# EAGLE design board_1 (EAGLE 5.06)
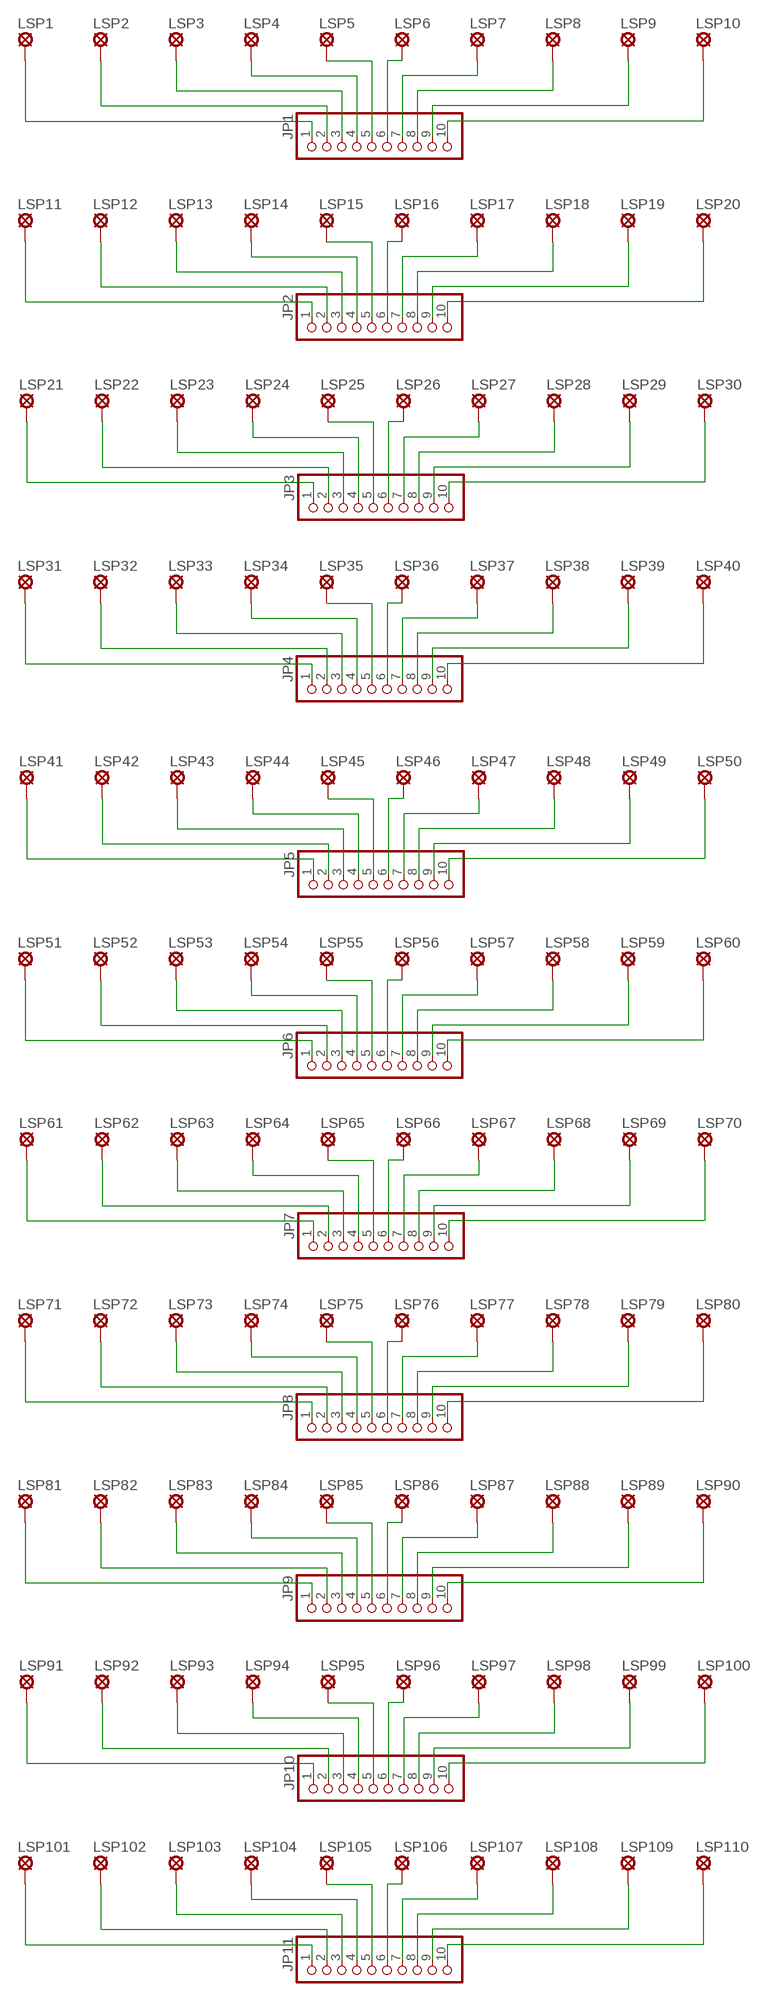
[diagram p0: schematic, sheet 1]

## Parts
JP1  PINHD-1X10  [1X10]
JP2  PINHD-1X10  [1X10]
JP3  PINHD-1X10  [1X10]
JP4  PINHD-1X10  [1X10]
JP5  PINHD-1X10  [1X10]
JP6  PINHD-1X10  [1X10]
JP7  PINHD-1X10  [1X10]
JP8  PINHD-1X10  [1X10]
JP9  PINHD-1X10  [1X10]
JP10  PINHD-1X10  [1X10]
JP11  PINHD-1X10  [1X10]
LSP1  LSP10MEDIUM_PAD2  [MEDIUM_PAD]
LSP2  LSP10MEDIUM_PAD2  [MEDIUM_PAD]
LSP3  LSP10MEDIUM_PAD2  [MEDIUM_PAD]
LSP4  LSP10MEDIUM_PAD2  [MEDIUM_PAD]
LSP5  LSP10MEDIUM_PAD2  [MEDIUM_PAD]
LSP6  LSP10MEDIUM_PAD2  [MEDIUM_PAD]
LSP7  LSP10MEDIUM_PAD2  [MEDIUM_PAD]
LSP8  LSP10MEDIUM_PAD2  [MEDIUM_PAD]
LSP9  LSP10MEDIUM_PAD2  [MEDIUM_PAD]
LSP10  LSP10MEDIUM_PAD2  [MEDIUM_PAD]
LSP11  LSP10MEDIUM_PAD2  [MEDIUM_PAD]
LSP12  LSP10MEDIUM_PAD2  [MEDIUM_PAD]
LSP13  LSP10MEDIUM_PAD2  [MEDIUM_PAD]
LSP14  LSP10MEDIUM_PAD2  [MEDIUM_PAD]
LSP15  LSP10MEDIUM_PAD2  [MEDIUM_PAD]
LSP16  LSP10MEDIUM_PAD2  [MEDIUM_PAD]
LSP17  LSP10MEDIUM_PAD2  [MEDIUM_PAD]
LSP18  LSP10MEDIUM_PAD2  [MEDIUM_PAD]
LSP19  LSP10MEDIUM_PAD2  [MEDIUM_PAD]
LSP20  LSP10MEDIUM_PAD2  [MEDIUM_PAD]
LSP21  LSP10MEDIUM_PAD2  [MEDIUM_PAD]
LSP22  LSP10MEDIUM_PAD2  [MEDIUM_PAD]
LSP23  LSP10MEDIUM_PAD2  [MEDIUM_PAD]
LSP24  LSP10MEDIUM_PAD2  [MEDIUM_PAD]
LSP25  LSP10MEDIUM_PAD2  [MEDIUM_PAD]
LSP26  LSP10MEDIUM_PAD2  [MEDIUM_PAD]
LSP27  LSP10MEDIUM_PAD2  [MEDIUM_PAD]
LSP28  LSP10MEDIUM_PAD2  [MEDIUM_PAD]
LSP29  LSP10MEDIUM_PAD2  [MEDIUM_PAD]
LSP30  LSP10MEDIUM_PAD2  [MEDIUM_PAD]
LSP31  LSP10MEDIUM_PAD2  [MEDIUM_PAD]
LSP32  LSP10MEDIUM_PAD2  [MEDIUM_PAD]
LSP33  LSP10MEDIUM_PAD2  [MEDIUM_PAD]
LSP34  LSP10MEDIUM_PAD2  [MEDIUM_PAD]
LSP35  LSP10MEDIUM_PAD2  [MEDIUM_PAD]
LSP36  LSP10MEDIUM_PAD2  [MEDIUM_PAD]
LSP37  LSP10MEDIUM_PAD2  [MEDIUM_PAD]
LSP38  LSP10MEDIUM_PAD2  [MEDIUM_PAD]
LSP39  LSP10MEDIUM_PAD2  [MEDIUM_PAD]
LSP40  LSP10MEDIUM_PAD2  [MEDIUM_PAD]
LSP41  LSP10MEDIUM_PAD2  [MEDIUM_PAD]
LSP42  LSP10MEDIUM_PAD2  [MEDIUM_PAD]
LSP43  LSP10MEDIUM_PAD2  [MEDIUM_PAD]
LSP44  LSP10MEDIUM_PAD2  [MEDIUM_PAD]
LSP45  LSP10MEDIUM_PAD2  [MEDIUM_PAD]
LSP46  LSP10MEDIUM_PAD2  [MEDIUM_PAD]
LSP47  LSP10MEDIUM_PAD2  [MEDIUM_PAD]
LSP48  LSP10MEDIUM_PAD2  [MEDIUM_PAD]
LSP49  LSP10MEDIUM_PAD2  [MEDIUM_PAD]
LSP50  LSP10MEDIUM_PAD2  [MEDIUM_PAD]
LSP51  LSP10MEDIUM_PAD2  [MEDIUM_PAD]
LSP52  LSP10MEDIUM_PAD2  [MEDIUM_PAD]
LSP53  LSP10MEDIUM_PAD2  [MEDIUM_PAD]
LSP54  LSP10MEDIUM_PAD2  [MEDIUM_PAD]
LSP55  LSP10MEDIUM_PAD2  [MEDIUM_PAD]
LSP56  LSP10MEDIUM_PAD2  [MEDIUM_PAD]
LSP57  LSP10MEDIUM_PAD2  [MEDIUM_PAD]
LSP58  LSP10MEDIUM_PAD2  [MEDIUM_PAD]
LSP59  LSP10MEDIUM_PAD2  [MEDIUM_PAD]
LSP60  LSP10MEDIUM_PAD2  [MEDIUM_PAD]
LSP61  LSP10MEDIUM_PAD2  [MEDIUM_PAD]
LSP62  LSP10MEDIUM_PAD2  [MEDIUM_PAD]
LSP63  LSP10MEDIUM_PAD2  [MEDIUM_PAD]
LSP64  LSP10MEDIUM_PAD2  [MEDIUM_PAD]
LSP65  LSP10MEDIUM_PAD2  [MEDIUM_PAD]
LSP66  LSP10MEDIUM_PAD2  [MEDIUM_PAD]
LSP67  LSP10MEDIUM_PAD2  [MEDIUM_PAD]
LSP68  LSP10MEDIUM_PAD2  [MEDIUM_PAD]
LSP69  LSP10MEDIUM_PAD2  [MEDIUM_PAD]
LSP70  LSP10MEDIUM_PAD2  [MEDIUM_PAD]
LSP71  LSP10MEDIUM_PAD2  [MEDIUM_PAD]
LSP72  LSP10MEDIUM_PAD2  [MEDIUM_PAD]
LSP73  LSP10MEDIUM_PAD2  [MEDIUM_PAD]
LSP74  LSP10MEDIUM_PAD2  [MEDIUM_PAD]
LSP75  LSP10MEDIUM_PAD2  [MEDIUM_PAD]
LSP76  LSP10MEDIUM_PAD2  [MEDIUM_PAD]
LSP77  LSP10MEDIUM_PAD2  [MEDIUM_PAD]
LSP78  LSP10MEDIUM_PAD2  [MEDIUM_PAD]
LSP79  LSP10MEDIUM_PAD2  [MEDIUM_PAD]
LSP80  LSP10MEDIUM_PAD2  [MEDIUM_PAD]
LSP81  LSP10MEDIUM_PAD2  [MEDIUM_PAD]
LSP82  LSP10MEDIUM_PAD2  [MEDIUM_PAD]
LSP83  LSP10MEDIUM_PAD2  [MEDIUM_PAD]
LSP84  LSP10MEDIUM_PAD2  [MEDIUM_PAD]
LSP85  LSP10MEDIUM_PAD2  [MEDIUM_PAD]
LSP86  LSP10MEDIUM_PAD2  [MEDIUM_PAD]
LSP87  LSP10MEDIUM_PAD2  [MEDIUM_PAD]
LSP88  LSP10MEDIUM_PAD2  [MEDIUM_PAD]
LSP89  LSP10MEDIUM_PAD2  [MEDIUM_PAD]
LSP90  LSP10MEDIUM_PAD2  [MEDIUM_PAD]
LSP91  LSP10MEDIUM_PAD2  [MEDIUM_PAD]
LSP92  LSP10MEDIUM_PAD2  [MEDIUM_PAD]
LSP93  LSP10MEDIUM_PAD2  [MEDIUM_PAD]
LSP94  LSP10MEDIUM_PAD2  [MEDIUM_PAD]
LSP95  LSP10MEDIUM_PAD2  [MEDIUM_PAD]
LSP96  LSP10MEDIUM_PAD2  [MEDIUM_PAD]
LSP97  LSP10MEDIUM_PAD2  [MEDIUM_PAD]
LSP98  LSP10MEDIUM_PAD2  [MEDIUM_PAD]
LSP99  LSP10MEDIUM_PAD2  [MEDIUM_PAD]
LSP100  LSP10MEDIUM_PAD2  [MEDIUM_PAD]
LSP101  LSP10MEDIUM_PAD2  [MEDIUM_PAD]
LSP102  LSP10MEDIUM_PAD2  [MEDIUM_PAD]
LSP103  LSP10MEDIUM_PAD2  [MEDIUM_PAD]
LSP104  LSP10MEDIUM_PAD2  [MEDIUM_PAD]
LSP105  LSP10MEDIUM_PAD2  [MEDIUM_PAD]
LSP106  LSP10MEDIUM_PAD2  [MEDIUM_PAD]
LSP107  LSP10MEDIUM_PAD2  [MEDIUM_PAD]
LSP108  LSP10MEDIUM_PAD2  [MEDIUM_PAD]
LSP109  LSP10MEDIUM_PAD2  [MEDIUM_PAD]
LSP110  LSP10MEDIUM_PAD2  [MEDIUM_PAD]

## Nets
N$1: JP1.1 LSP1.P$1(MP)
N$2: JP1.2 LSP2.P$1(MP)
N$3: JP1.3 LSP3.P$1(MP)
N$4: JP1.4 LSP4.P$1(MP)
N$5: JP1.5 LSP5.P$1(MP)
N$6: JP1.6 LSP6.P$1(MP)
N$7: JP1.7 LSP7.P$1(MP)
N$8: JP1.8 LSP8.P$1(MP)
N$9: JP1.9 LSP9.P$1(MP)
N$10: JP1.10 LSP10.P$1(MP)
N$19: JP2.1 LSP11.P$1(MP)
N$20: JP2.2 LSP12.P$1(MP)
N$21: JP2.3 LSP13.P$1(MP)
N$22: JP2.4 LSP14.P$1(MP)
N$23: JP2.5 LSP15.P$1(MP)
N$24: JP2.6 LSP16.P$1(MP)
N$25: JP2.7 LSP17.P$1(MP)
N$26: JP2.8 LSP18.P$1(MP)
N$27: JP2.9 LSP19.P$1(MP)
N$28: JP2.10 LSP20.P$1(MP)
N$29: JP3.1 LSP21.P$1(MP)
N$30: JP3.2 LSP22.P$1(MP)
N$31: JP3.3 LSP23.P$1(MP)
N$32: JP3.4 LSP24.P$1(MP)
N$33: JP3.5 LSP25.P$1(MP)
N$34: JP3.6 LSP26.P$1(MP)
N$35: JP3.7 LSP27.P$1(MP)
N$36: JP3.8 LSP28.P$1(MP)
N$37: JP3.9 LSP29.P$1(MP)
N$38: JP3.10 LSP30.P$1(MP)
N$39: JP4.1 LSP31.P$1(MP)
N$40: JP4.2 LSP32.P$1(MP)
N$41: JP4.3 LSP33.P$1(MP)
N$42: JP4.4 LSP34.P$1(MP)
N$43: JP4.5 LSP35.P$1(MP)
N$44: JP4.6 LSP36.P$1(MP)
N$45: JP4.7 LSP37.P$1(MP)
N$46: JP4.8 LSP38.P$1(MP)
N$47: JP4.9 LSP39.P$1(MP)
N$48: JP4.10 LSP40.P$1(MP)
N$49: JP5.1 LSP41.P$1(MP)
N$50: JP5.2 LSP42.P$1(MP)
N$51: JP5.3 LSP43.P$1(MP)
N$52: JP5.4 LSP44.P$1(MP)
N$53: JP5.5 LSP45.P$1(MP)
N$54: JP5.6 LSP46.P$1(MP)
N$55: JP5.7 LSP47.P$1(MP)
N$56: JP5.8 LSP48.P$1(MP)
N$57: JP5.9 LSP49.P$1(MP)
N$58: JP5.10 LSP50.P$1(MP)
N$59: JP6.1 LSP51.P$1(MP)
N$60: JP6.2 LSP52.P$1(MP)
N$61: JP6.3 LSP53.P$1(MP)
N$62: JP6.4 LSP54.P$1(MP)
N$63: JP6.5 LSP55.P$1(MP)
N$64: JP6.6 LSP56.P$1(MP)
N$65: JP6.7 LSP57.P$1(MP)
N$66: JP6.8 LSP58.P$1(MP)
N$67: JP6.9 LSP59.P$1(MP)
N$68: JP6.10 LSP60.P$1(MP)
N$69: JP7.1 LSP61.P$1(MP)
N$70: JP7.2 LSP62.P$1(MP)
N$71: JP7.3 LSP63.P$1(MP)
N$72: JP7.4 LSP64.P$1(MP)
N$73: JP7.5 LSP65.P$1(MP)
N$74: JP7.6 LSP66.P$1(MP)
N$75: JP7.7 LSP67.P$1(MP)
N$76: JP7.8 LSP68.P$1(MP)
N$77: JP7.9 LSP69.P$1(MP)
N$78: JP7.10 LSP70.P$1(MP)
N$79: JP8.1 LSP71.P$1(MP)
N$80: JP8.2 LSP72.P$1(MP)
N$81: JP8.3 LSP73.P$1(MP)
N$82: JP8.4 LSP74.P$1(MP)
N$83: JP8.5 LSP75.P$1(MP)
N$84: JP8.6 LSP76.P$1(MP)
N$85: JP8.7 LSP77.P$1(MP)
N$86: JP8.8 LSP78.P$1(MP)
N$87: JP8.9 LSP79.P$1(MP)
N$88: JP8.10 LSP80.P$1(MP)
N$89: JP9.1 LSP81.P$1(MP)
N$90: JP9.2 LSP82.P$1(MP)
N$91: JP9.3 LSP83.P$1(MP)
N$92: JP9.4 LSP84.P$1(MP)
N$93: JP9.5 LSP85.P$1(MP)
N$94: JP9.6 LSP86.P$1(MP)
N$95: JP9.7 LSP87.P$1(MP)
N$96: JP9.8 LSP88.P$1(MP)
N$97: JP9.9 LSP89.P$1(MP)
N$98: JP9.10 LSP90.P$1(MP)
N$99: JP10.1 LSP91.P$1(MP)
N$100: JP10.2 LSP92.P$1(MP)
N$101: JP10.3 LSP93.P$1(MP)
N$102: JP10.4 LSP94.P$1(MP)
N$103: JP10.5 LSP95.P$1(MP)
N$104: JP10.6 LSP96.P$1(MP)
N$105: JP10.7 LSP97.P$1(MP)
N$106: JP10.8 LSP98.P$1(MP)
N$107: JP10.9 LSP99.P$1(MP)
N$108: JP10.10 LSP100.P$1(MP)
N$109: JP11.1 LSP101.P$1(MP)
N$110: JP11.2 LSP102.P$1(MP)
N$111: JP11.3 LSP103.P$1(MP)
N$112: JP11.4 LSP104.P$1(MP)
N$113: JP11.5 LSP105.P$1(MP)
N$114: JP11.6 LSP106.P$1(MP)
N$115: JP11.7 LSP107.P$1(MP)
N$116: JP11.8 LSP108.P$1(MP)
N$117: JP11.9 LSP109.P$1(MP)
N$118: JP11.10 LSP110.P$1(MP)

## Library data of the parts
JP1-JP11 = pinhead:PINHD-1X10: PIN HEADER
LSP1-LSP110 = solpad:LSP10: SOLDER PAD

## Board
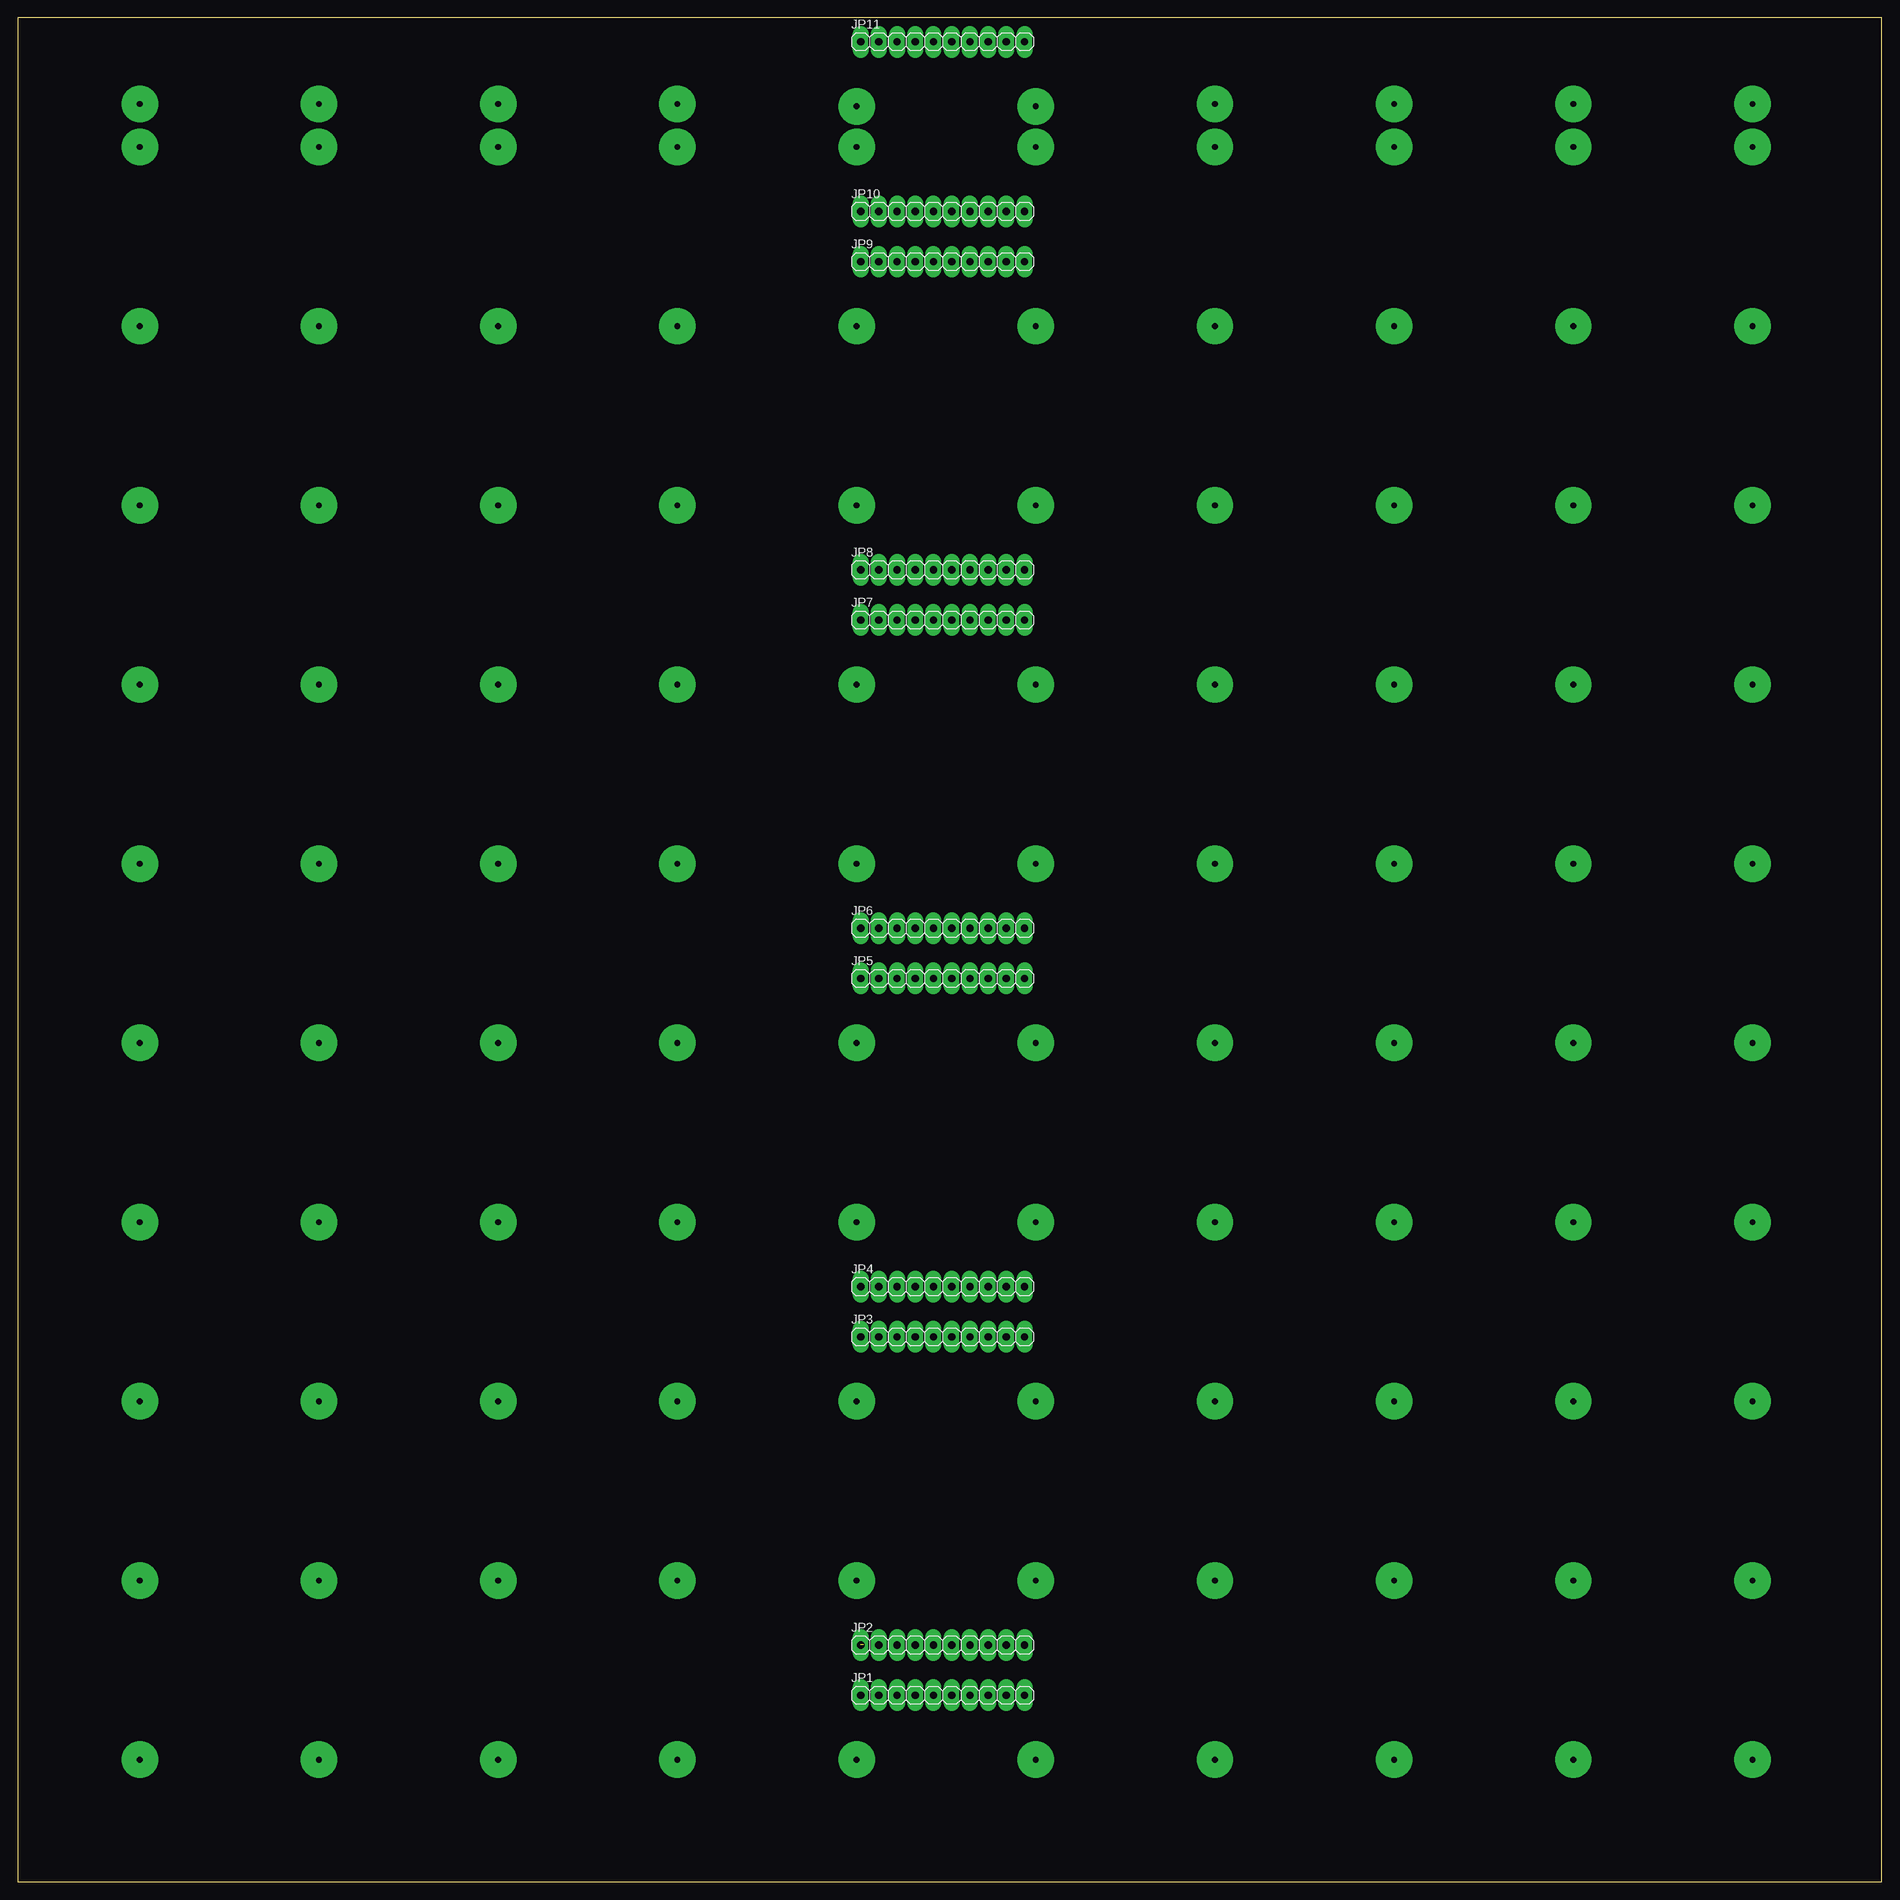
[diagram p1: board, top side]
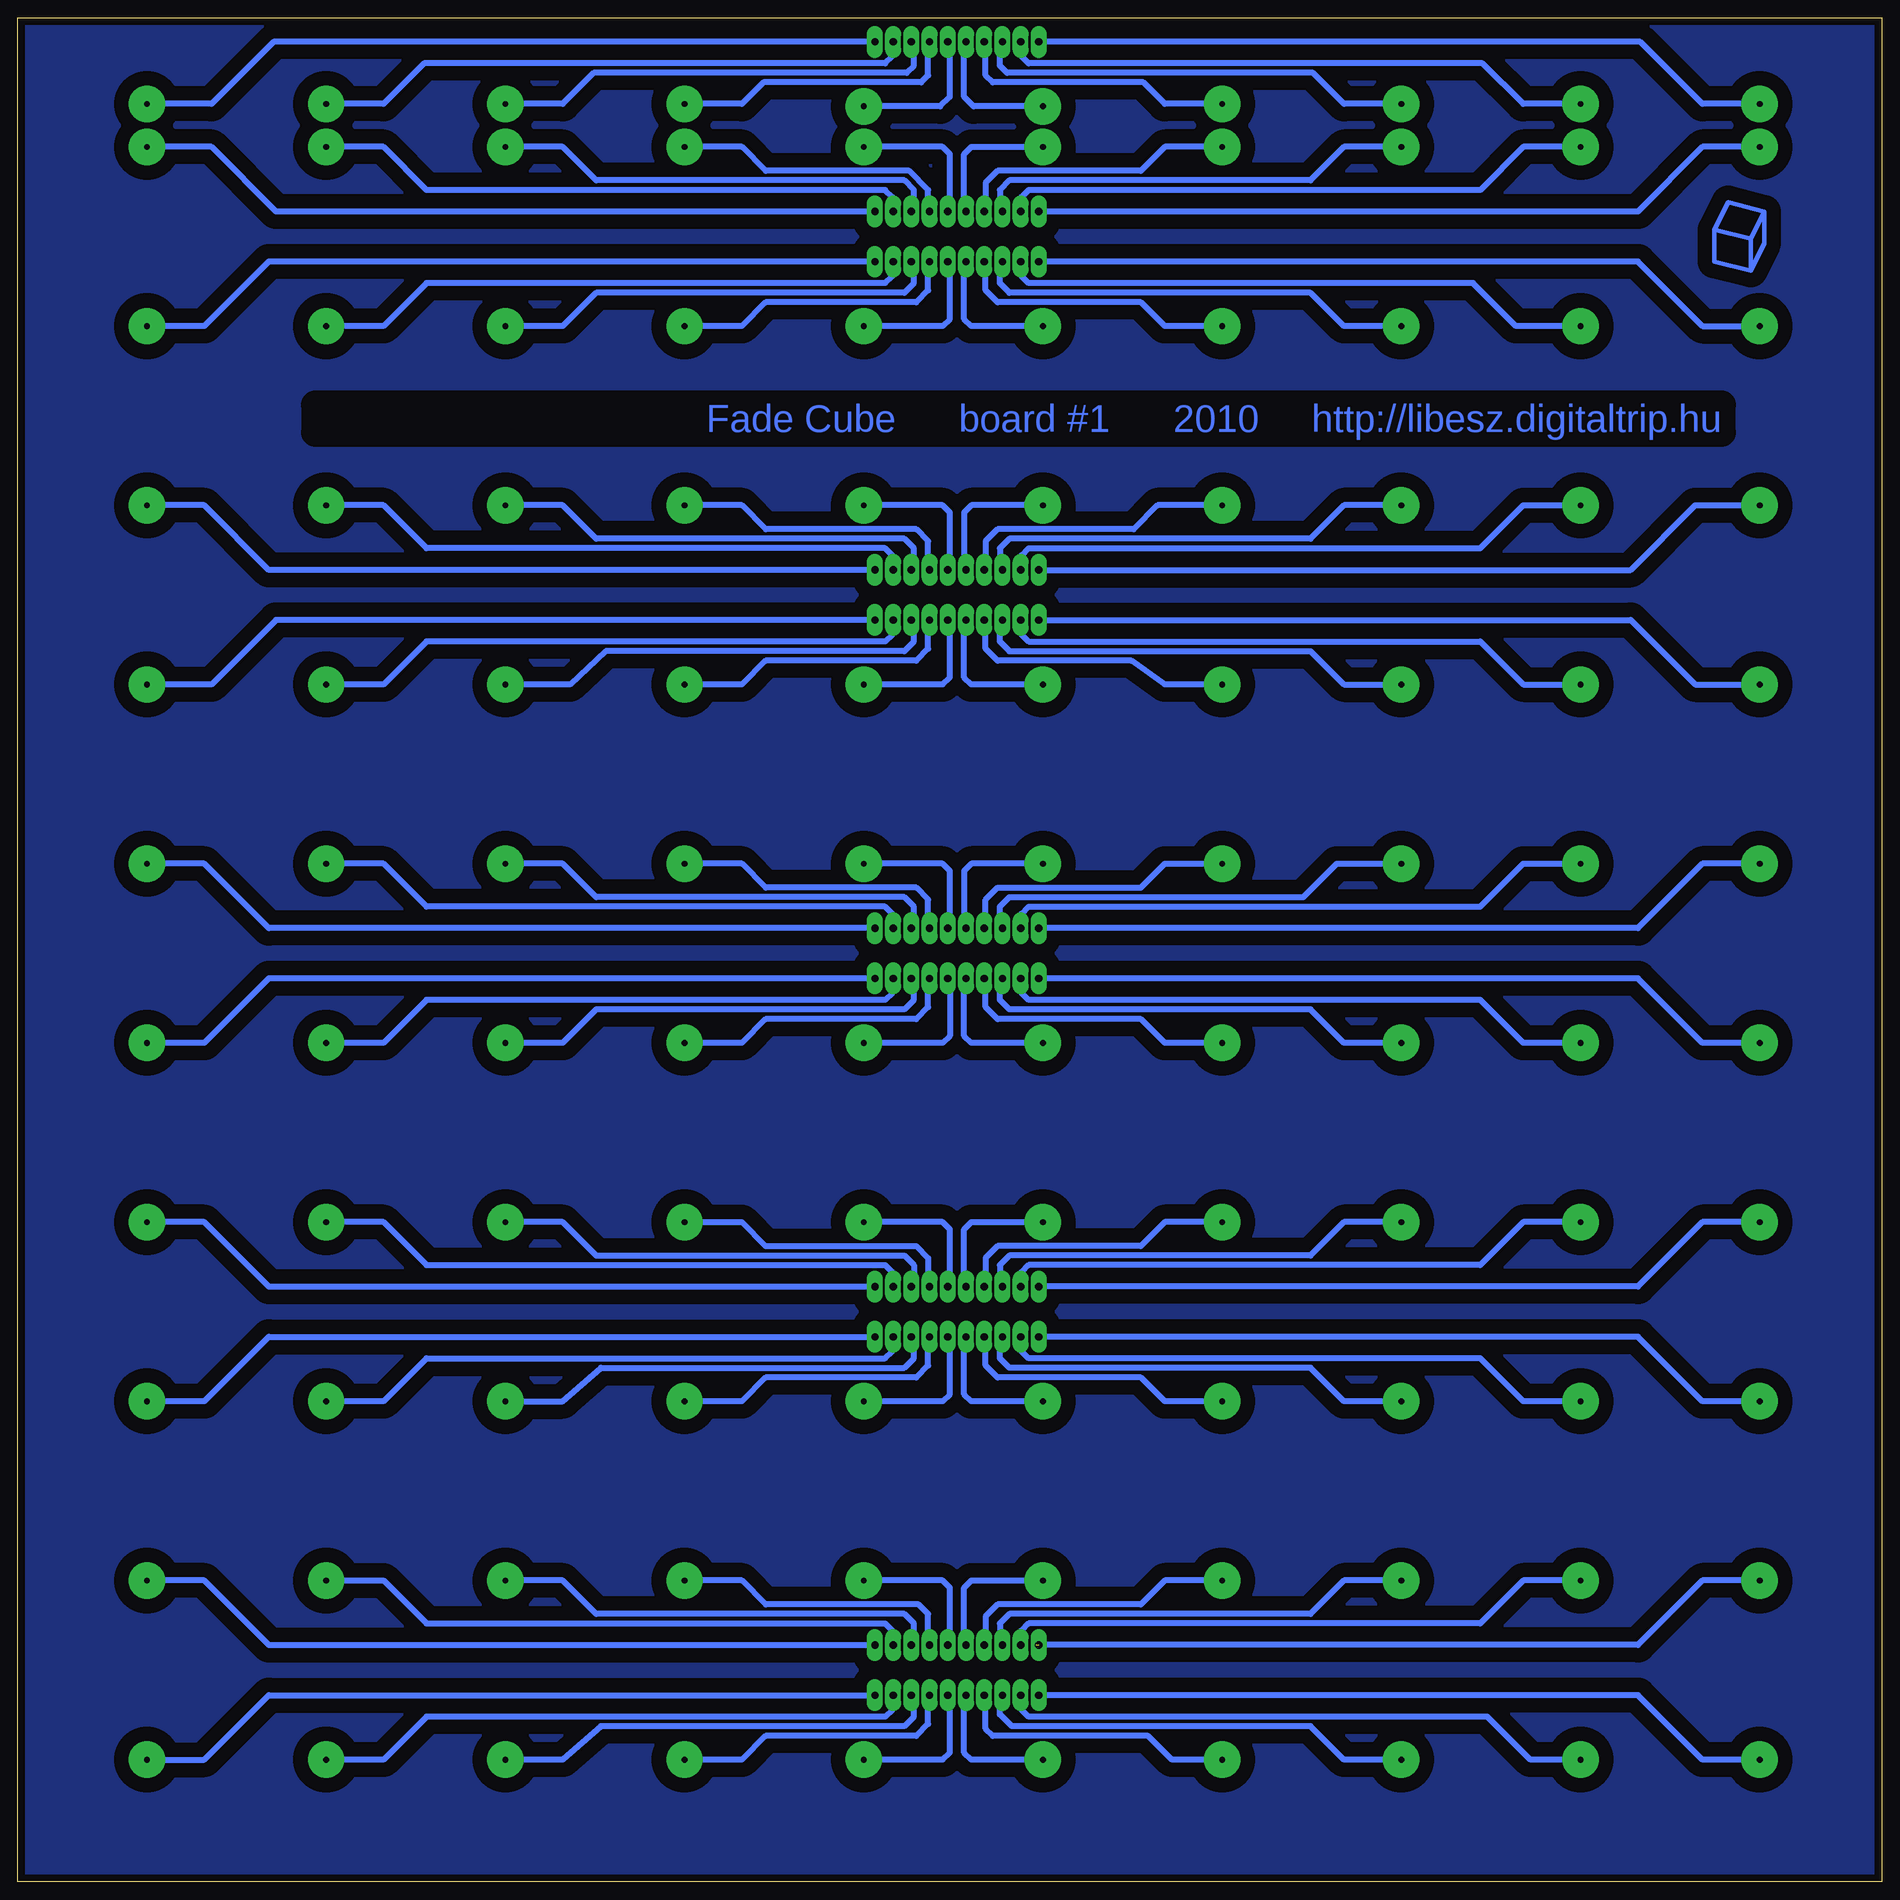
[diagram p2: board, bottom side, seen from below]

Size 260 x 260 mm. Coordinates in mm from the lower left corner, seen from the top.
Outline: 0,0 260,0 260,260 0,260 0,0
Copper layers (1*16): Top 0.035mm / dielectric 1.5mm / Bottom 0.035mm
Design rules "hobby *": minimum track width 0.8mm, minimum drill 0.8mm, track to track 80mil, track to pad 80mil, pad to pad 80mil, via to via 80mil, smd to smd 8mil, copper to edge 40mil, drill to drill 8mil, minimum pad ring 0.6mm, minimum via ring 0.6mm, stop-mask expansion 4mil, vias tented up to drill 0mil, thermal gap 10mil

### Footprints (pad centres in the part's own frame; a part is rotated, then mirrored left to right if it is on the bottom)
1X10 = drill 1.016 long: 1 -11.43,0; 2 -8.89,0; 3 -6.35,0; 4 -3.81,0; 5 -1.27,0; 6 1.27,0; 7 3.81,0; 8 6.35,0; 9 8.89,0; 10 11.43,0
MEDIUM_PAD = drill 0.8 pad 5.08 round: P$1 0,0

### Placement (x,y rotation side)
JP1  129,26 0 top
JP2  129,33 0 top
JP3  129,76 0 top
JP4  129,83 0 top
JP5  129,126 0 top
JP6  129,133 0 top
JP7  129,176 0 top
JP8  129,183 0 top
JP9  129,226 0 top
JP10  129,233 0 top
JP11  129,256.67 0 top
LSP1  17,17 0 top
LSP2  42,17 0 top
LSP3  67,17 0 top
LSP4  92,17 0 top
LSP5  117,17 0 top
LSP6  142,17 0 top
LSP7  167,17 0 top
LSP8  192,17 0 top
LSP9  217,17 0 top
LSP10  242,17 0 top
LSP11  17,42 0 top
LSP12  42,42 0 top
LSP13  67,42 0 top
LSP14  92,42 0 top
LSP15  117,42 0 top
LSP16  142,42 0 top
LSP17  167,42 0 top
LSP18  192,42 0 top
LSP19  217,42 0 top
LSP20  242,42 0 top
LSP21  17,67 0 top
LSP22  42,67 0 top
LSP23  67,67 0 top
LSP24  92,67 0 top
LSP25  117,67 0 top
LSP26  142,67 0 top
LSP27  167,67 0 top
LSP28  192,67 0 top
LSP29  217,67 0 top
LSP30  242,67 0 top
LSP31  17,92 0 top
LSP32  42,92 0 top
LSP33  67,92 0 top
LSP34  92,92 0 top
LSP35  117,92 0 top
LSP36  142,92 0 top
LSP37  167,92 0 top
LSP38  192,92 0 top
LSP39  217,92 0 top
LSP40  242,92 0 top
LSP41  17,117 0 top
LSP42  42,117 0 top
LSP43  67,117 0 top
LSP44  92,117 0 top
LSP45  117,117 0 top
LSP46  142,117 0 top
LSP47  167,117 0 top
LSP48  192,117 0 top
LSP49  217,117 0 top
LSP50  242,117 0 top
LSP51  17,142 0 top
LSP52  42,142 0 top
LSP53  67,142 0 top
LSP54  92,142 0 top
LSP55  117,142 0 top
LSP56  142,142 0 top
LSP57  167,142 0 top
LSP58  192,142 0 top
LSP59  217,142 0 top
LSP60  242,142 0 top
LSP61  17,167 0 top
LSP62  42,167 0 top
LSP63  67,167 0 top
LSP64  92,167 0 top
LSP65  117,167 0 top
LSP66  142,167 0 top
LSP67  167,167 0 top
LSP68  192,167 0 top
LSP69  217,167 0 top
LSP70  242,167 0 top
LSP71  17,192 0 top
LSP72  42,192 0 top
LSP73  67,192 0 top
LSP74  92,192 0 top
LSP75  117,192 0 top
LSP76  142,192 0 top
LSP77  167,192 0 top
LSP78  192,192 0 top
LSP79  217,192 0 top
LSP80  242,192 0 top
LSP81  17,217 0 top
LSP82  42,217 0 top
LSP83  67,217 0 top
LSP84  92,217 0 top
LSP85  117,217 0 top
LSP86  142,217 0 top
LSP87  167,217 0 top
LSP88  192,217 0 top
LSP89  217,217 0 top
LSP90  242,217 0 top
LSP91  17,242 0 top
LSP92  42,242 0 top
LSP93  67,242 0 top
LSP94  92,242 0 top
LSP95  117,242 0 top
LSP96  142,242 0 top
LSP97  167,242 0 top
LSP98  192,242 0 top
LSP99  217,242 0 top
LSP100  242,242 0 top
LSP101  17,248 0 top
LSP102  42,248 0 top
LSP103  67,248 0 top
LSP104  92,248 0 top
LSP105  117,247.67 0 top
LSP106  142,247.67 0 top
LSP107  167,248 0 top
LSP108  192,248 0 top
LSP109  217,248 0 top
LSP110  242,248 0 top
U$1  [CUBE_LOGO]  16.33,233 0 top

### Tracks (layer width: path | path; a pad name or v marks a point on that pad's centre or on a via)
N$1
  Bottom 0.813: LSP1.P$1 25,17 34,26 JP1.1
N$2
  Bottom 0.813: LSP2.P$1 49,17 55,23 119,23 120,24 120,25.89 JP1.2
N$3
  Bottom 0.813: LSP3.P$1 75,17 79.67,21.67 121.33,21.67 123,23.33 123,25.65 JP1.3
N$4
  Bottom 0.813: LSP4.P$1 99,17 102.33,20.33 124,20.33 125,21.33 125,25.81 JP1.4
N$5
  Bottom 0.813: LSP5.P$1 127,17 128,18 128,25.73 JP1.5
N$6
  Bottom 0.813: LSP6.P$1 131,17 130,18 130,25.73 JP1.6
N$7
  Bottom 0.813: LSP7.P$1 159,17 155.67,20.33 134.67,20.33 133,22 133,25.81 JP1.7
N$8
  Bottom 0.813: LSP8.P$1 184,17 178.67,21.67 136.33,21.67 135,23 135,25.65 JP1.8
N$9
  Bottom 0.813: LSP9.P$1 209,17 203,23 139,23 138,24 138,25.89 JP1.9
N$10
  Bottom 0.813: LSP10.P$1 234,17 225,26 JP1.10
N$11
  pour Bottom: -0.33,261 260.67,261 260.67,-1 -0.67,-1
N$19  (1 unrouted)
  Bottom 0.813: LSP11.P$1 25,42 34,33 118,33
N$20
  Bottom 0.813: LSP12.P$1 50,42 56,36 119,36 120,35 120,33.11 JP2.2
N$21
  Bottom 0.813: LSP13.P$1 75,42 79.67,37.33 121.67,37.33 123,36 123,33.35 JP2.3
N$22
  Bottom 0.813: LSP14.P$1 100,42 103.33,38.67 123.33,38.67 125,37 125,33.19 JP2.4
N$23
  Bottom 0.813: LSP15.P$1 127,42 128,41 128,33.27 JP2.5
N$24
  Bottom 0.813: LSP16.P$1 131,42 130,41 130,33.27 JP2.6
N$25
  Bottom 0.813: LSP17.P$1 159,42 155.67,38.67 134.33,38.67 133,37.33 133,33.19 JP2.7
N$26
  Bottom 0.813: LSP18.P$1 184,42 179.33,37.33 136.33,37.33 135,36 135,33.35 JP2.8
N$27
  Bottom 0.813: LSP19.P$1 209,42 203,36 139,36 138,35 138,33.11 JP2.9
N$28
  Bottom 0.813: LSP20.P$1 234,42 225,33 JP2.10
N$29
  Bottom 0.813: LSP21.P$1 25,67 34,76 JP3.1
N$30
  Bottom 0.813: LSP22.P$1 50,67 56,73 119,73 120,74 120,75.89 JP3.2
N$31
  Bottom 0.813: LSP23.P$1 75,67 79.67,71.67 121.67,71.67 123,73 123,75.65 JP3.3
N$32
  Bottom 0.813: LSP24.P$1 100,67 103.33,70.33 123.33,70.33 125,72 125,75.81 JP3.4
N$33
  Bottom 0.813: LSP25.P$1 127,67 128,68 128,75.73 JP3.5
N$34
  Bottom 0.813: LSP26.P$1 131,67 130,68 130,75.73 JP3.6
N$35
  Bottom 0.813: LSP27.P$1 159,67 155.67,70.33 134.67,70.33 133,72 133,75.81 JP3.7
N$36
  Bottom 0.813: LSP28.P$1 184,67 178.67,71.67 136.33,71.67 135,73 135,75.65 JP3.8
N$37
  Bottom 0.813: LSP29.P$1 209,67 203,73 139,73 138,74 138,75.89 JP3.9
N$38
  Bottom 0.813: LSP30.P$1 234,67 225,76 JP3.10
N$39
  Bottom 0.813: LSP31.P$1 25,92 34,83 JP4.1
N$40
  Bottom 0.813: LSP32.P$1 50,92 56,86 119,86 120,85 120,83.11 JP4.2
N$41
  Bottom 0.813: LSP33.P$1 75,92 79.67,87.33 121.67,87.33 123,86 123,83.35 JP4.3
N$42
  Bottom 0.813: LSP34.P$1 100,92 103.33,88.67 123.33,88.67 125,87 125,83.19 JP4.4
N$43
  Bottom 0.813: LSP35.P$1 127,92 128,91 128,83.27 JP4.5
N$44
  Bottom 0.813: LSP36.P$1 131,92 130,91 130,83.27 JP4.6
N$45
  Bottom 0.813: LSP37.P$1 159,92 155.67,88.67 134.67,88.67 133,87 133,83.19 JP4.7
N$46
  Bottom 0.813: LSP38.P$1 184,92 179.33,87.33 136.33,87.33 135,86 135,83.35 JP4.8
N$47
  Bottom 0.813: LSP39.P$1 209,92 203,86 139,86 138,85 138,83.11 JP4.9
N$48
  Bottom 0.813: LSP40.P$1 234,92 225,83 JP4.10
N$49
  Bottom 0.813: LSP41.P$1 25,117 34,126 JP5.1
N$50
  Bottom 0.813: LSP42.P$1 50,117 56,123 119,123 120,124 120,126.89 JP5.2
N$51
  Bottom 0.813: LSP43.P$1 75,117 79.67,121.67 121.67,121.67 123,123 123,126.65 JP5.3
N$52
  Bottom 0.813: LSP44.P$1 100,117 103.33,120.33 123.33,120.33 125,122 125,126.81 JP5.4
N$53
  Bottom 0.813: LSP45.P$1 127,117 128,118 128,126.73 JP5.5
N$54
  Bottom 0.813: LSP46.P$1 131,117 130,118 130,126.73 JP5.6
N$55
  Bottom 0.813: LSP47.P$1 159,117 155.67,120.33 134.67,120.33 133,122 133,126.81 JP5.7
N$56
  Bottom 0.813: LSP48.P$1 184,117 179.33,121.67 136.33,121.67 135,123 135,126.65 JP5.8
N$57
  Bottom 0.813: LSP49.P$1 209,117 203,123 139,123 138,124 138,126.89 JP5.9
N$58
  Bottom 0.813: LSP50.P$1 234,117 225,126 JP5.10
N$59
  Bottom 0.813: LSP51.P$1 25,142 34,133 JP6.1
N$60
  Bottom 0.813: LSP52.P$1 50,142 56,136 119,136 120,135 120,133.11 JP6.2
N$61
  Bottom 0.813: LSP53.P$1 76,142 80.67,137.33 121.67,137.33 123,136 123,134.35 JP6.3
N$62
  Bottom 0.813: LSP54.P$1 100,142 103.33,138.67 123.33,138.67 125,137 125,134.19 JP6.4
N$63
  Bottom 0.813: LSP55.P$1 127,142 128,141 128,134.27 JP6.5
N$64
  Bottom 0.813: LSP56.P$1 131,142 130,141 130,134.27 JP6.6
N$65
  Bottom 0.813: LSP57.P$1 159,142 155.67,138.67 134.67,138.67 133,137 133,133.19 JP6.7
N$66
  Bottom 0.813: LSP58.P$1 184,142 179.33,137.33 136.33,137.33 135,136 135,133.35 JP6.8
N$67
  Bottom 0.813: LSP59.P$1 209,142 203,136 139,136 138,135 138,133.11 JP6.9
N$68
  Bottom 0.813: LSP60.P$1 234,142 225,133 JP6.10
N$69
  Bottom 0.813: LSP61.P$1 26,167 35,176 JP7.1
N$70
  Bottom 0.813: LSP62.P$1 50,167 56,173 119,173 120,174 120,175.89 JP7.2
N$71
  Bottom 0.813: LSP63.P$1 75,167 79.67,171.67 121.67,171.67 123,173 123,175.65 JP7.3
N$72
  Bottom 0.813: LSP64.P$1 100,167 104.67,170.33 123.33,170.33 125,172 125,175.81 JP7.4
N$73
  Bottom 0.813: LSP65.P$1 127,167 128,168 128,174.73 JP7.5
N$74
  Bottom 0.813: LSP66.P$1 131,167 130,168 130,174.73 JP7.6
N$75
  Bottom 0.813: LSP67.P$1 159,167 155.67,170.33 134.67,170.33 133,172 133,174.81 JP7.7
N$76
  Bottom 0.813: LSP68.P$1 183,167 178,171.67 136.33,171.67 135,173 135,174.65 JP7.8
N$77
  Bottom 0.813: LSP69.P$1 209,167 203,173 139,173 138,174 138,175.89 JP7.9
N$78
  Bottom 0.813: LSP70.P$1 233,167 224,176 JP7.10
N$79
  Bottom 0.813: LSP71.P$1 26,192 35,183 JP8.1
N$80
  Bottom 0.813: LSP72.P$1 50,192 56,186 119,186 120,185 120,183.11 JP8.2
N$81
  Bottom 0.813: LSP73.P$1 75,192 79.67,187.33 121.67,187.33 123,186 123,183.35 JP8.3
N$82
  Bottom 0.813: LSP74.P$1 101,192 104.33,188.67 123.33,188.67 125,187 125,183.19 JP8.4
N$83
  Bottom 0.813: LSP75.P$1 127,192 128,191 128,183.27 JP8.5
N$84
  Bottom 0.813: LSP76.P$1 131,192 130,191 130,183.27 JP8.6
N$85
  Bottom 0.813: LSP77.P$1 159,192 155.67,188.67 134.67,188.67 133,187 133,183.19 JP8.7
N$86
  Bottom 0.813: LSP78.P$1 184,192 179.33,187.33 136.33,187.33 135,186 135,183.35 JP8.8
N$87
  Bottom 0.813: LSP79.P$1 209,192 203,186 139,186 138,185 138,183.11 JP8.9
N$88
  Bottom 0.813: LSP80.P$1 234,192 225,183 JP8.10
N$89
  Bottom 0.813: LSP81.P$1 25,217 34,226 JP9.1
N$90
  Bottom 0.813: LSP82.P$1 51,217 57,223 119,223 120,224 120,225.89 JP9.2
N$91
  Bottom 0.813: LSP83.P$1 75,217 79.67,221.67 121.67,221.67 123,223 123,224.65 JP9.3
N$92
  Bottom 0.813: LSP84.P$1 100,217 103.33,220.33 123.33,220.33 125,222 125,224.81 JP9.4
N$93
  Bottom 0.813: LSP85.P$1 127,217 128,218 128,224.73 JP9.5
N$94
  Bottom 0.813: LSP86.P$1 131,217 130,218 130,224.73 JP9.6
N$95
  Bottom 0.813: LSP87.P$1 159,217 155.67,220.33 134.67,220.33 133,222 133,225.81 JP9.7
N$96
  Bottom 0.813: LSP88.P$1 184,217 179.33,221.67 136.33,221.67 135,223 135,225.65 JP9.8
N$97
  Bottom 0.813: LSP89.P$1 209,217 203,223 139,223 138,224 138,225.89 JP9.9
N$98
  Bottom 0.813: LSP90.P$1 234,217 225,226 JP9.10
N$99
  Bottom 0.813: LSP91.P$1 25,242 34,233 JP10.1
N$100
  Bottom 0.813: LSP92.P$1 50,242 56,236 119,236 120,235 120,233.11 JP10.2
N$101
  Bottom 0.813: LSP93.P$1 75,242 79.67,237.33 121.67,237.33 123,236 123,233.35 JP10.3
N$102
  Bottom 0.813: LSP94.P$1 100,242 103.33,238.67 123.33,238.67 125,237 125,233.19 JP10.4
N$103
  Bottom 0.813: LSP95.P$1 127,242 128,241 128,233.27 JP10.5
N$104
  Bottom 0.813: LSP96.P$1 131,242 130,241 130,233.27 JP10.6
N$105
  Bottom 0.813: LSP97.P$1 159,242 155.67,238.67 135.67,238.67 133,236 133,233.19 JP10.7
N$106
  Bottom 0.813: LSP98.P$1 184,242 179.33,237.33 136.33,237.33 135,236 135,233.35 JP10.8
N$107
  Bottom 0.813: LSP99.P$1 209,242 203,236 139,236 138,235 138,233.11 JP10.9
N$108
  Bottom 0.813: LSP100.P$1 233,242 224,233 JP10.10 140,233
N$109
  Bottom 0.813: LSP101.P$1 25,248 33.67,256.67 JP11.1
N$110
  Bottom 0.813: LSP102.P$1 50,248 55.67,253.67 119,253.67 120,254.67 120,255.89 JP11.2
N$111
  Bottom 0.813: LSP103.P$1 75,248 79.33,252.33 122,252.33 123,253.33 123,255.65 JP11.3
N$112
  Bottom 0.813: LSP104.P$1 100,248 103,251 124,251 125,252 125,255.81 JP11.4
N$113
  Bottom 0.813: LSP105.P$1 126.67,247.67 128,249 128,255.73 JP11.5
N$114
  Bottom 0.813: LSP106.P$1 131.33,247.67 130,249 130,255.73 JP11.6
N$115
  Bottom 0.813: LSP107.P$1 159,248 156,251 134,251 133,252 133,255.81 JP11.7
N$116
  Bottom 0.813: LSP108.P$1 184,248 179.67,252.33 136,252.33 135,253.33 135,255.65 JP11.8
N$117
  Bottom 0.813: LSP109.P$1 209,248 203.33,253.67 139,253.67 138,254.67 138,255.89 JP11.9
N$118
  Bottom 0.813: LSP110.P$1 233,248 224.33,256.67 JP11.10

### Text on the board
Bottom: Fade Cube board #1 2010 http://libesz.digitaltrip.hu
